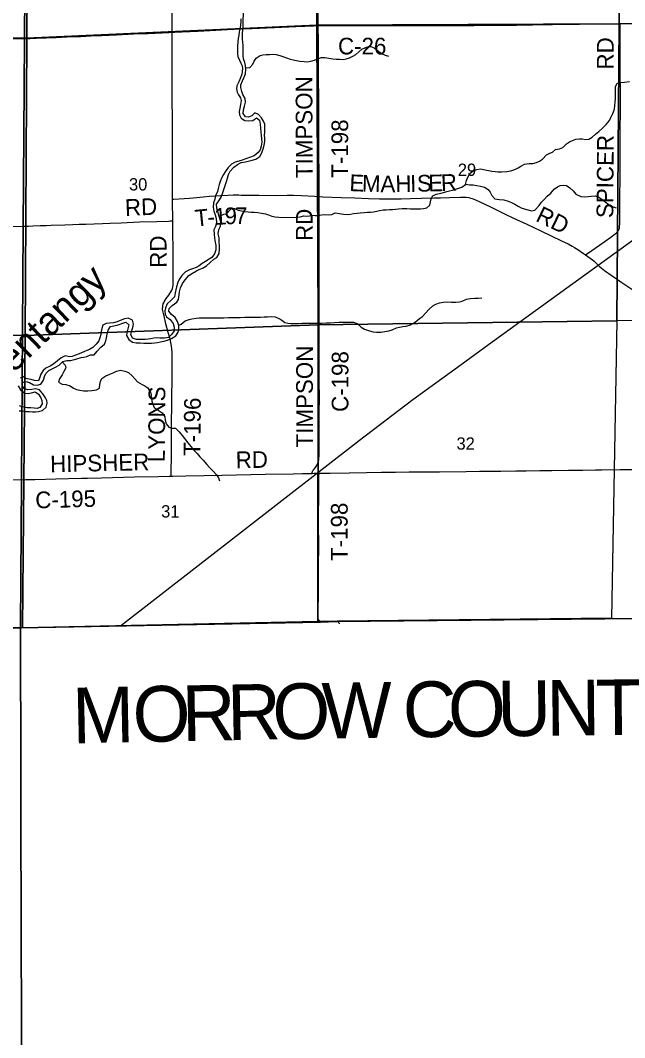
# Model space of a CAD drawing. Extents: x 1584893 to 1934202, y 663575 to 1091909.
# Drawn here: x 1841383 to 1852245, y 956462 to 974741 of the extents above; entities that cross this region are included whole.
import ezdxf

# ---------------------------------------------------------------- set-up
doc = ezdxf.new("R2010")
doc.units = 0
for name, color, linetype in [('GM_X_Adjacent_County', 7, 'Continuous'), ('GM_X_Adjacent_County_Text', 7, 'Continuous'), ('GM_X_County', 7, 'Continuous'), ('GM_X_County_Road', 7, 'Continuous'), ('GM_X_County_Road_Text', 7, 'Continuous'), ('GM_X_Major_River', 7, 'Continuous'), ('GM_X_Major_River_Text', 7, 'Continuous'), ('GM_X_Minor_River', 7, 'Continuous'), ('GM_X_Rail_Line', 7, 'Continuous'), ('GM_X_Section', 7, 'Continuous'), ('GM_X_Section_Text', 7, 'Continuous'), ('GM_X_Township', 7, 'Continuous'), ('GM_X_Township_Road', 7, 'Continuous'), ('GM_X_Township_Road_Text', 7, 'Continuous')]:
    doc.layers.add(name, color=color, linetype=linetype)

msp = doc.modelspace()

# ---------------------------------------------------------------- linework, layer by layer
at = {"layer": 'GM_X_Adjacent_County'}
msp.add_lwpolyline([(1841392, 953202), (1841402, 956488), (1841397, 958575), (1841394, 960342), (1841392, 961182), (1841387, 963824), (1846780, 963929), (1847071, 963938), (1852487, 963992)], dxfattribs=at)
at = {"layer": 'GM_X_County'}
msp.add_lwpolyline([(1852487, 963992), (1847071, 963938), (1846780, 963929), (1841387, 963824), (1841392, 961182), (1841394, 960342), (1841397, 958575), (1841402, 956488), (1841392, 953202)], dxfattribs=at)
at = {"layer": 'GM_X_County_Road'}
for points in [[(1844110, 974526), (1844159, 974530), (1844284, 974536), (1844575, 974549), (1844895, 974566), (1845109, 974576), (1845355, 974588), (1845543, 974594), (1845952, 974613), (1846333, 974631), (1846659, 974644), (1846738, 974647)], [(1846738, 974647), (1846837, 974649), (1847430, 974648), (1847919, 974647), (1848394, 974648), (1848749, 974649), (1849020, 974647), (1849342, 974647), (1849536, 974649), (1849766, 974652), (1850304, 974656), (1850586, 974661), (1850950, 974664), (1851210, 974671), (1851432, 974673), (1851731, 974680), (1852054, 974681), (1852165, 974681)], [(1852165, 974681), (1852339, 974685), (1852528, 974686), (1852724, 974689), (1853041, 974695), (1853330, 974698), (1853643, 974698), (1853900, 974702), (1854097, 974707), (1854466, 974710), (1854695, 974714), (1854798, 974712)], [(1838155, 974444), (1838418, 974444), (1838648, 974441), (1838861, 974440), (1839107, 974439), (1839501, 974434), (1839878, 974430), (1840174, 974426), (1840387, 974425), (1840764, 974422), (1841076, 974417), (1841289, 974415), (1841535, 974415), (1841560, 974416)], [(1841560, 974416), (1841666, 974419), (1842027, 974435), (1842224, 974444), (1842470, 974452), (1842650, 974462), (1842847, 974471), (1843109, 974481), (1843420, 974496), (1843683, 974507), (1844060, 974522), (1844110, 974526)], [(1846627, 966601), (1846630, 966618), (1846634, 966636), (1846643, 966652), (1846656, 966668), (1846687, 966707), (1846705, 966735), (1846721, 966764), (1846728, 966779), (1846738, 966811), (1846746, 966843), (1846751, 966876), (1846753, 966909), (1846755, 967014), (1846756, 967405), (1846757, 967712), (1846758, 967941), (1846756, 968269), (1846756, 968859), (1846755, 969039), (1846757, 969219), (1846757, 969400), (1846757, 969662), (1846755, 970153), (1846756, 970678), (1846756, 970907), (1846755, 971104), (1846755, 971284), (1846756, 971448), (1846755, 971546), (1846755, 971576)], [(1844092, 966552), (1844121, 966552), (1844356, 966555), (1844684, 966562), (1845013, 966569), (1845268, 966576), (1845783, 966585), (1846287, 966593), (1846456, 966598), (1846627, 966601)], [(1846627, 966601), (1846665, 966602), (1846752, 966603)], [(1846752, 966603), (1846767, 966603), (1846950, 966607), (1847292, 966612), (1847604, 966616), (1847874, 966621), (1848124, 966624), (1848374, 966626), (1848674, 966629), (1848916, 966631), (1849395, 966635), (1849634, 966639), (1850021, 966643), (1850287, 966645), (1850473, 966647), (1850721, 966650), (1850934, 966653), (1851237, 966657), (1851494, 966660), (1851721, 966662), (1851836, 966663), (1852164, 966668), (1852420, 966671)], [(1841169, 966484), (1841473, 966488)], [(1841473, 966488), (1841645, 966490), (1842022, 966501), (1842482, 966513), (1842590, 966515), (1842843, 966521), (1843433, 966536), (1843860, 966546), (1844060, 966552), (1844092, 966552)]]:
    msp.add_lwpolyline(points, dxfattribs=at)
at = {"layer": 'GM_X_Major_River'}
for points in [[(1845749, 972434), (1845766, 972496), (1845775, 972562), (1845775, 972624), (1845774, 972680), (1845777, 972730), (1845780, 972804), (1845778, 972876), (1845755, 972927), (1845720, 972992), (1845665, 973047), (1845600, 973077), (1845543, 973028), (1845481, 972999), (1845427, 973006), (1845386, 973065), (1845393, 973135), (1845409, 973199), (1845428, 973271), (1845422, 973339), (1845383, 973408), (1845362, 973463), (1845346, 973533), (1845345, 973583), (1845376, 973653), (1845399, 973705), (1845431, 973780), (1845437, 973862), (1845430, 973931), (1845417, 973981), (1845393, 974050), (1845388, 974112), (1845387, 974162), (1845388, 974212), (1845386, 974280), (1845381, 974353), (1845378, 974403), (1845377, 974453), (1845378, 974509), (1845382, 974563), (1845387, 974635), (1845391, 974707), (1845395, 974894)], [(1845346, 974767), (1845349, 974716), (1845342, 974658), (1845335, 974606), (1845317, 974535), (1845308, 974469), (1845300, 974415), (1845293, 974351), (1845288, 974284), (1845286, 974212), (1845289, 974144), (1845294, 974090), (1845320, 974027), (1845347, 973974), (1845368, 973924), (1845375, 973874), (1845372, 973823), (1845363, 973772), (1845342, 973708), (1845310, 973638), (1845277, 973567), (1845267, 973513), (1845282, 973452), (1845307, 973400), (1845338, 973349), (1845355, 973298), (1845341, 973226), (1845326, 973165), (1845319, 973103), (1845322, 973044), (1845352, 972982), (1845417, 972944), (1845485, 972933), (1845561, 972939), (1845626, 972992), (1845683, 972947), (1845696, 972874), (1845702, 972804), (1845707, 972734)], [(1845707, 972734), (1845714, 972673), (1845716, 972619), (1845721, 972551), (1845714, 972483), (1845692, 972417), (1845657, 972364), (1845584, 972305), (1845499, 972275), (1845435, 972254), (1845368, 972229), (1845310, 972210), (1845246, 972192), (1845177, 972155), (1845120, 972094), (1845066, 972021), (1845033, 971970), (1845004, 971916), (1844972, 971844), (1844957, 971793), (1844940, 971721), (1844925, 971667), (1844893, 971585), (1844876, 971528), (1844856, 971462), (1844849, 971384), (1844859, 971315), (1844884, 971247), (1844902, 971178), (1844909, 971104), (1844891, 971038), (1844862, 970974), (1844864, 970898), (1844873, 970826), (1844887, 970757), (1844894, 970695), (1844895, 970619), (1844873, 970545), (1844826, 970482), (1844775, 970449), (1844712, 970408), (1844651, 970371), (1844596, 970328), (1844544, 970301), (1844475, 970275), (1844423, 970258), (1844350, 970221), (1844283, 970156), (1844235, 970085), (1844214, 970031), (1844187, 969950), (1844178, 969896), (1844166, 969842), (1844151, 969770), (1844088, 969707), (1844022, 969648), (1843991, 969577), (1843980, 969519), (1843986, 969463), (1844011, 969412), (1844076, 969364), (1844131, 969295), (1844147, 969225), (1844148, 969164), (1844105, 969105), (1844044, 969042), (1843975, 969032), (1843893, 969031), (1843839, 969035), (1843781, 969028), (1843731, 969017), (1843681, 969012), (1843625, 969007), (1843545, 969005), (1843469, 969006), (1843400, 969030), (1843371, 969096), (1843384, 969168), (1843402, 969224), (1843415, 969282), (1843396, 969355), (1843321, 969392), (1843255, 969380), (1843176, 969349), (1843124, 969326), (1843056, 969308), (1842983, 969297), (1842925, 969292), (1842867, 969261), (1842845, 969204), (1842836, 969150), (1842829, 969098), (1842814, 969034), (1842795, 968982), (1842747, 968921), (1842686, 968860), (1842626, 968827), (1842575, 968810), (1842521, 968785), (1842440, 968747), (1842377, 968722)], [(1841896, 968447), (1841952, 968478), (1842017, 968509), (1842082, 968548), (1842149, 968609), (1842218, 968631), (1842284, 968632), (1842334, 968641), (1842396, 968658), (1842475, 968684), (1842525, 968689), (1842575, 968700), (1842641, 968729), (1842710, 968733), (1842765, 968798), (1842828, 968869), (1842893, 968922), (1842921, 968983), (1842934, 969035), (1842945, 969105), (1842959, 969173), (1843004, 969242), (1843066, 969253), (1843139, 969270), (1843207, 969294), (1843278, 969319), (1843335, 969268), (1843313, 969196), (1843296, 969128), (1843293, 969078), (1843333, 969007), (1843398, 968960), (1843466, 968946), (1843538, 968947), (1843604, 968943), (1843738, 968940), (1843796, 968945), (1843846, 968954), (1843902, 968963), (1843962, 968978), (1844029, 968996), (1844099, 969023), (1844178, 969072), (1844220, 969139), (1844231, 969193), (1844232, 969255), (1844208, 969332), (1844165, 969403), (1844098, 969458), (1844052, 969513), (1844055, 969563), (1844112, 969618), (1844195, 969677), (1844226, 969728), (1844238, 969810), (1844243, 969860), (1844264, 969936), (1844298, 970012), (1844345, 970081), (1844411, 970154), (1844476, 970200), (1844547, 970239), (1844599, 970264), (1844656, 970289), (1844728, 970330), (1844796, 970392), (1844861, 970447), (1844912, 970482), (1844955, 970551), (1844961, 970629), (1844960, 970688), (1844959, 970760), (1844955, 970834), (1844941, 970905), (1844948, 970985), (1844981, 971044), (1844989, 971110), (1844968, 971179), (1844950, 971241), (1844933, 971300), (1844914, 971368), (1844908, 971437), (1844951, 971500), (1844990, 971561), (1845016, 971627), (1845039, 971703), (1845056, 971754), (1845086, 971846), (1845106, 971908), (1845127, 971968), (1845152, 972031), (1845218, 972104), (1845289, 972153), (1845355, 972185), (1845428, 972200), (1845480, 972209), (1845548, 972228), (1845617, 972248), (1845688, 972295), (1845725, 972362), (1845749, 972434)], [(1842377, 968722), (1842317, 968703), (1842267, 968696), (1842191, 968714), (1842117, 968679), (1842053, 968625), (1841982, 968572), (1841916, 968529), (1841843, 968491), (1841792, 968452), (1841751, 968384), (1841735, 968328), (1841708, 968261), (1841638, 968272), (1841577, 968286), (1841507, 968301), (1841470, 968313)], [(1841359, 967723), (1841427, 967723), (1841482, 967714), (1841546, 967711), (1841600, 967708), (1841658, 967706), (1841712, 967711), (1841781, 967732), (1841844, 967789), (1841867, 967860), (1841856, 967911), (1841832, 967961), (1841785, 968029), (1841725, 968102), (1841657, 968117), (1841589, 968105), (1841517, 968102), (1841453, 968126), (1841416, 968177), (1841415, 968233), (1841482, 968251), (1841547, 968234), (1841617, 968192), (1841684, 968183), (1841753, 968206), (1841800, 968273), (1841816, 968339), (1841839, 968394), (1841896, 968447)], [(1841470, 968313), (1841438, 968337), (1841377, 968310)], [(1841344, 968174), (1841383, 968103), (1841455, 968043), (1841521, 968038), (1841582, 968051), (1841652, 968065), (1841711, 968026), (1841750, 967961), (1841767, 967911), (1841773, 967848), (1841736, 967785), (1841686, 967768), (1841632, 967771), (1841574, 967776), (1841504, 967776), (1841418, 967798), (1841367, 967813)]]:
    msp.add_lwpolyline(points, dxfattribs=at)
at = {"layer": 'GM_X_Minor_River'}
for points in [[(1845435, 973885), (1845505, 973891), (1845559, 973954), (1845588, 974009), (1845619, 974063), (1845694, 974108), (1845744, 974119), (1845800, 974127), (1845860, 974130), (1845926, 974131), (1845982, 974126), (1846046, 974110), (1846103, 974089), (1846165, 974068), (1846232, 974046), (1846288, 974031), (1846344, 974020), (1846407, 974008), (1846485, 973999), (1846537, 973998), (1846607, 974008), (1846668, 974025), (1846740, 974058), (1846795, 974073), (1846855, 974071), (1846926, 974062), (1847002, 974052), (1847068, 974045), (1847122, 974042), (1847184, 974040), (1847238, 974049), (1847302, 974070), (1847361, 974095), (1847414, 974130), (1847467, 974175), (1847524, 974222), (1847576, 974247), (1847630, 974266), (1847683, 974269), (1847742, 974247), (1847797, 974202), (1847874, 974146), (1847943, 974117), (1847999, 974100)], [(1850949, 972372), (1851002, 972419), (1851073, 972435), (1851135, 972456), (1851202, 972523), (1851253, 972556), (1851306, 972583), (1851368, 972604), (1851432, 972612), (1851484, 972611), (1851550, 972602), (1851600, 972607), (1851659, 972640), (1851722, 972696), (1851783, 972745), (1851842, 972800), (1851915, 972869), (1851971, 972940), (1851994, 972998), (1852030, 973067), (1852063, 973145), (1852071, 973211), (1852076, 973271), (1852081, 973335), (1852081, 973407), (1852079, 973493), (1852078, 973549), (1852111, 973609), (1852177, 973621), (1852243, 973630), (1852330, 973640)], [(1844959, 971212), (1844973, 971221), (1845040, 971260), (1845094, 971262), (1845129, 971314), (1845182, 971367), (1845234, 971358), (1845301, 971330), (1845357, 971317), (1845415, 971308), (1845477, 971303), (1845529, 971297), (1845585, 971294), (1845650, 971287), (1845720, 971279), (1845790, 971262), (1845843, 971245), (1845905, 971223), (1845961, 971210), (1846029, 971207), (1846288, 971201), (1846340, 971202), (1846414, 971211), (1846477, 971226), (1846529, 971222), (1846581, 971227), (1846631, 971238), (1846683, 971237), (1846739, 971234), (1846795, 971245), (1846847, 971252), (1846925, 971246), (1846981, 971255), (1847040, 971280), (1847122, 971272), (1847193, 971259), (1847261, 971255), (1847315, 971260), (1847371, 971269), (1847438, 971278), (1847490, 971283), (1847560, 971291), (1847620, 971294), (1847676, 971295), (1847730, 971298), (1847788, 971311), (1847838, 971322), (1847903, 971334), (1847957, 971339), (1848019, 971340), (1848071, 971345), (1848129, 971350), (1848183, 971356), (1848249, 971361), (1848329, 971359), (1848397, 971356), (1848457, 971355), (1848513, 971354), (1848575, 971356), (1848631, 971361), (1848689, 971370), (1848746, 971419), (1848757, 971481), (1848766, 971533), (1848798, 971590), (1848856, 971619), (1848920, 971630), (1848991, 971650), (1849047, 971667), (1849099, 971680), (1849150, 971691), (1849204, 971708), (1849262, 971725), (1849317, 971742), (1849384, 971789), (1849405, 971864), (1849428, 971926), (1849460, 971990), (1849527, 972044), (1849589, 972063), (1849657, 972072), (1849735, 972056), (1849797, 972041), (1849857, 972032), (1849916, 972024), (1849968, 972019), (1850030, 972018), (1850128, 972026), (1850199, 972038), (1850273, 972059), (1850332, 972088), (1850382, 972119), (1850443, 972156), (1850527, 972168), (1850595, 972169), (1850663, 972185), (1850716, 972210), (1850771, 972249), (1850840, 972322), (1850899, 972353), (1850949, 972372)], [(1849386, 971798), (1849457, 971783), (1849525, 971784), (1849587, 971776), (1849655, 971759), (1849726, 971743), (1849794, 971704), (1849827, 971653), (1849855, 971596), (1849914, 971533), (1849996, 971519), (1850076, 971514), (1850151, 971494), (1850214, 971465), (1850270, 971435), (1850329, 971400), (1850384, 971375), (1850440, 971356), (1850502, 971336), (1850569, 971319), (1850631, 971330), (1850711, 971414), (1850752, 971473), (1850806, 971528), (1850853, 971580), (1850916, 971638), (1850979, 971705), (1851036, 971750), (1851089, 971773), (1851141, 971780), (1851201, 971771), (1851260, 971732), (1851317, 971680), (1851369, 971615), (1851456, 971575), (1851516, 971570), (1851590, 971576), (1851644, 971583), (1851714, 971586), (1851780, 971562), (1851839, 971521), (1851918, 971461), (1851973, 971426), (1852040, 971392), (1852092, 971373)], [(1844230, 969261), (1844273, 969282), (1844348, 969339), (1844416, 969367), (1844466, 969376), (1844541, 969389), (1844595, 969394), (1844645, 969397), (1844709, 969397), (1844903, 969393), (1844971, 969394), (1845043, 969394), (1845127, 969399), (1845185, 969400), (1845259, 969400), (1845335, 969402), (1845417, 969405), (1845491, 969407), (1845557, 969408), (1845627, 969410), (1845699, 969409), (1845765, 969416), (1845823, 969416), (1845893, 969417), (1845961, 969415), (1846032, 969386), (1846085, 969353), (1846139, 969314), (1846190, 969300), (1846244, 969295), (1846316, 969296), (1846386, 969296), (1846442, 969299), (1846498, 969300), (1846588, 969300), (1846644, 969301), (1846702, 969300), (1846796, 969302), (1846880, 969304), (1846956, 969307), (1847030, 969313), (1847106, 969317), (1847164, 969316), (1847228, 969315), (1847300, 969317), (1847372, 969318), (1847438, 969292), (1847508, 969229), (1847569, 969189), (1847657, 969160), (1847726, 969142), (1847782, 969139), (1847860, 969139), (1847936, 969148), (1848005, 969160), (1848069, 969183), (1848144, 969214), (1848200, 969228), (1848256, 969241), (1848320, 969246), (1848397, 969268), (1848482, 969319), (1848557, 969381), (1848610, 969418), (1848667, 969479), (1848727, 969546), (1848796, 969611), (1848850, 969640), (1848919, 969665), (1848991, 969679), (1849069, 969684), (1849135, 969680), (1849211, 969679), (1849275, 969683), (1849325, 969694), (1849404, 969729), (1849476, 969743), (1849554, 969748), (1849610, 969749), (1849679, 969753)], [(1842138, 968599), (1842190, 968548), (1842201, 968495), (1842167, 968432), (1842132, 968370), (1842085, 968299), (1842067, 968237), (1842133, 968204), (1842200, 968198), (1842276, 968171), (1842341, 968133), (1842394, 968108), (1842454, 968095), (1842516, 968084), (1842598, 968086), (1842670, 968092), (1842750, 968099), (1842807, 968132), (1842814, 968200), (1842823, 968252), (1842846, 968307), (1842921, 968356), (1842994, 968384), (1843053, 968409), (1843111, 968438), (1843184, 968457), (1843261, 968439), (1843327, 968412), (1843391, 968356), (1843440, 968301), (1843489, 968248), (1843572, 968198), (1843623, 968171), (1843677, 968136), (1843725, 968062), (1843734, 968004), (1843741, 967948), (1843747, 967897), (1843764, 967843), (1843791, 967786), (1843880, 967724), (1843935, 967689), (1843977, 967616), (1843986, 967558), (1844001, 967491), (1844052, 967430), (1844107, 967415), (1844169, 967413), (1844238, 967346), (1844290, 967282), (1844331, 967228), (1844394, 967152), (1844450, 967083), (1844509, 967013), (1844559, 966956), (1844612, 966897), (1844669, 966837), (1844733, 966760), (1844780, 966709), (1844847, 966643), (1844911, 966576), (1844942, 966523), (1844961, 966464)]]:
    msp.add_lwpolyline(points, dxfattribs=at)
at = {"layer": 'GM_X_Rail_Line'}
msp.add_lwpolyline([(1843186, 963859), (1847480, 967198), (1848435, 967928), (1849305, 968558), (1849800, 968917), (1855926, 973347)], dxfattribs=at)
at = {"layer": 'GM_X_Section'}
for points in [[(1852199, 980028), (1857493, 980105), (1857385, 974712), (1852149, 974677)], [(1841535, 979712), (1844949, 979989), (1846705, 980015), (1846710, 974657), (1841497, 974418)], [(1846705, 980015), (1852199, 980028), (1852149, 974677), (1846710, 974657)], [(1836169, 979777), (1841535, 979712), (1841497, 974418), (1836118, 974458)], [(1841497, 974418), (1846710, 974657), (1846738, 969270), (1841469, 969077)], [(1846710, 974657), (1852149, 974677), (1852104, 969344), (1846738, 969270)], [(1852149, 974677), (1857385, 974712), (1857325, 969408), (1852104, 969344)], [(1836118, 974458), (1841497, 974418), (1841469, 969077), (1836100, 969135)], [(1846738, 969270), (1852104, 969344), (1852006, 963999), (1847086, 963946), (1846730, 963939)], [(1836100, 969135), (1841469, 969077), (1841420, 963828), (1836085, 963804)], [(1841469, 969077), (1846738, 969270), (1846730, 963939), (1841420, 963828)]]:
    msp.add_lwpolyline(points, close=True, dxfattribs=at)
at = {"layer": 'GM_X_Township'}
for points in [[(1852487, 963992), (1847071, 963938), (1846780, 963929), (1841387, 963824), (1841405, 966456), (1841436, 971009), (1841459, 974382), (1841496, 979677), (1841532, 984992), (1841533, 985009), (1841872, 985027), (1842914, 985093), (1844196, 985194), (1845074, 985259), (1845572, 985289), (1846658, 985379), (1846800, 985384), (1849534, 985395), (1852293, 985374)], [(1809298, 953687), (1809358, 958555), (1809388, 963837), (1815539, 963824), (1823776, 963824), (1832077, 963824), (1839237, 963824), (1841387, 963824), (1841392, 961182), (1841394, 960342), (1841397, 958575), (1841402, 956488), (1841392, 953202)]]:
    msp.add_lwpolyline(points, dxfattribs=at)
msp.add_lwpolyline([(1809388, 963837), (1809397, 965194), (1809409, 966524), (1809470, 974481), (1809490, 979763), (1809554, 985051), (1810918, 985033), (1820580, 985048), (1828627, 985061), (1836217, 985098), (1839819, 985043), (1841171, 985014), (1841533, 985009), (1841532, 984992), (1841496, 979677), (1841459, 974382), (1841436, 971009), (1841405, 966456), (1841387, 963824), (1839237, 963824), (1832077, 963824), (1823776, 963824), (1815539, 963824)], close=True, dxfattribs=at)
at = {"layer": 'GM_X_Township_Road'}
for points in [[(1844110, 974526), (1844110, 974576), (1844110, 974708), (1844114, 975053)], [(1846738, 974647), (1846738, 974720), (1846735, 974983)], [(1846755, 971576), (1846755, 971768), (1846755, 971957), (1846751, 972365), (1846750, 972644), (1846749, 972775), (1846748, 972988), (1846748, 973153), (1846748, 973333), (1846745, 973711), (1846743, 973908), (1846743, 974051), (1846741, 974229), (1846740, 974402), (1846739, 974597), (1846738, 974647)], [(1851540, 970525), (1851566, 970544), (1851579, 970553), (1851793, 970704), (1851994, 970845), (1852077, 970903), (1852098, 970921), (1852111, 970935), (1852122, 970947), (1852131, 970961), (1852139, 970975), (1852145, 970990), (1852152, 971008), (1852155, 971028), (1852156, 971099), (1852156, 971152), (1852156, 971205), (1852156, 971272), (1852159, 971349), (1852158, 971431), (1852161, 971653), (1852164, 971824), (1852166, 972184), (1852165, 972430), (1852165, 972828), (1852169, 973053), (1852169, 973298), (1852168, 973478), (1852166, 973773), (1852166, 973937), (1852166, 974084), (1852166, 974379), (1852164, 974595), (1852164, 974641), (1852165, 974681)], [(1844119, 971527), (1844118, 971838), (1844119, 972199), (1844117, 972543), (1844115, 972822), (1844115, 972970), (1844113, 973314), (1844113, 973658), (1844111, 973954), (1844110, 974265), (1844110, 974478), (1844110, 974526)], [(1844119, 971527), (1844142, 971528), (1844328, 971540), (1844426, 971548), (1844488, 971554)], [(1844125, 971138), (1844124, 971165), (1844119, 971477), (1844119, 971527)], [(1844488, 971554), (1844671, 971572), (1844785, 971581), (1844982, 971594), (1845113, 971600), (1845211, 971603), (1845310, 971603), (1845351, 971602)], [(1845351, 971602), (1845474, 971598), (1845671, 971597), (1845966, 971595), (1846180, 971597), (1846292, 971600), (1846434, 971595), (1846669, 971581), (1846755, 971576)], [(1846755, 971576), (1846819, 971571), (1847147, 971559), (1847393, 971550), (1847639, 971539), (1847836, 971533), (1847934, 971532), (1848066, 971531), (1848230, 971533), (1848394, 971537), (1848591, 971544), (1848820, 971549), (1848935, 971552), (1849099, 971558), (1849296, 971566), (1849345, 971566), (1849394, 971563), (1849443, 971555), (1849475, 971547), (1849506, 971537), (1849567, 971513), (1849642, 971479), (1849834, 971387), (1850085, 971265), (1850234, 971195), (1850486, 971076), (1850738, 970956), (1851108, 970780), (1851227, 970724), (1851300, 970686), (1851346, 970661), (1851401, 970626), (1851505, 970550), (1851540, 970525)], [(1841737, 971052), (1841738, 971052), (1841853, 971057), (1841934, 971060), (1842180, 971068), (1842328, 971073), (1842442, 971076), (1842557, 971081), (1842704, 971086), (1842862, 971092), (1842995, 971096), (1843195, 971105), (1843523, 971118), (1843834, 971128), (1844047, 971135), (1844080, 971136), (1844125, 971138)], [(1844067, 969034), (1844039, 969135), (1844000, 969288), (1843966, 969429), (1843954, 969475), (1843945, 969519), (1843941, 969552), (1843941, 969571), (1843942, 969585), (1843946, 969619), (1843952, 969647), (1843959, 969666), (1843968, 969685), (1843984, 969714), (1844002, 969741), (1844053, 969805), (1844072, 969832), (1844089, 969860), (1844104, 969890), (1844115, 969920), (1844124, 969952), (1844129, 969984), (1844132, 970017), (1844132, 970070), (1844131, 970361), (1844129, 970640), (1844126, 970919), (1844125, 971138)], [(1841247, 971034), (1841443, 971041), (1841531, 971044)], [(1841531, 971044), (1841607, 971047), (1841737, 971052)], [(1851540, 970525), (1851665, 970435), (1851696, 970411), (1851728, 970382), (1851775, 970337), (1851787, 970326)], [(1851787, 970326), (1851824, 970295), (1851883, 970248), (1852021, 970149), (1852195, 970031), (1852391, 969901)], [(1844092, 966552), (1844092, 966582), (1844094, 966633), (1844097, 966919), (1844099, 967247), (1844102, 967543), (1844105, 967786), (1844106, 967922), (1844108, 968070), (1844109, 968200), (1844112, 968461), (1844113, 968688), (1844112, 968773), (1844107, 968838), (1844101, 968887), (1844089, 968951), (1844082, 968981), (1844074, 969012), (1844067, 969034)], [(1846765, 963942), (1846758, 963950), (1846749, 963960), (1846743, 963974), (1846739, 963997), (1846736, 964044), (1846739, 964155), (1846741, 964408), (1846743, 964649), (1846745, 964960), (1846747, 965289), (1846744, 965699), (1846744, 965879), (1846747, 966164), (1846751, 966469), (1846751, 966552), (1846752, 966603)], [(1846926, 963935), (1846923, 963935), (1846841, 963930), (1846809, 963931), (1846792, 963933), (1846779, 963935), (1846772, 963938), (1846765, 963942)], [(1847120, 963897), (1847117, 963903), (1847113, 963910), (1847107, 963917), (1847100, 963924), (1847087, 963932), (1847071, 963938), (1847054, 963940), (1847022, 963941), (1846926, 963935)]]:
    msp.add_lwpolyline(points, dxfattribs=at)

# ---------------------------------------------------------------- texts
at = {"layer": 'GM_X_Adjacent_County_Text'}
for s, rotation, p in [('M', 1.1566, (1842325, 961749)), ('O', 1.1538, (1843411, 961771)), ('R', 1.1378, (1844296, 961789)), ('R', 1.0787, (1845109, 961805)), ('O', 0.9602, (1845922, 961820)), ('W', 0.8568, (1846806, 961835)), ('C', 0.6817, (1848262, 961857)), ('O', 0.6166, (1849075, 961866)), ('U', 0.597, (1849960, 961876)), ('N', 0.5981, (1850844, 961885)), ('T', 0.5979, (1851728, 961894))]:
    msp.add_text(s, height=1000, rotation=rotation, dxfattribs=at).set_placement(p)
at = {"layer": 'GM_X_County_Road_Text'}
for s, rotation, p in [('C-26', 0, (1847093, 974128)), ('RD', 90, (1846636, 970777)), ('TIMPSON', 90, (1846641, 967068)), ('C-198', 90.0011, (1847280, 967705)), ('HIPSHER', 1.2838, (1841921, 966619)), ('RD', 0.9872, (1845256, 966693)), ('C-195', 1.6641, (1841655, 965971))]:
    msp.add_text(s, height=300, rotation=rotation, dxfattribs=at).set_placement(p)
at = {"layer": 'GM_X_Major_River_Text'}
msp.add_text('Olentangy', height=500.1, rotation=44.0104, dxfattribs=at).set_placement((1840773, 967921))
at = {"layer": 'GM_X_Section_Text'}
for s, p in [('29', (1849247, 971946)), ('30', (1843336, 971684)), ('32', (1849223, 967027)), ('31', (1843914, 965808))]:
    msp.add_text(s, height=221, rotation=0, dxfattribs=at).set_placement(p)
at = {"layer": 'GM_X_Township_Road_Text'}
for s, rotation, p in [('RD', 90, (1852048, 973857)), ('TIMPSON', 90.1555, (1846636, 971908)), ('T-198', 90, (1847275, 971913)), ('SPICER', 89.5982, (1852040, 971187)), ('E', 357.6551, (1847293, 971674)), ('M', 357.9534, (1847519, 971665)), ('A', 359.8892, (1847856, 971653)), ('H', 1.2243, (1848127, 971653)), ('I', 1.2964, (1848392, 971658)), ('S', 1.2958, (1848515, 971661)), ('E', 1.3506, (1848718, 971666)), ('R', 2.4548, (1848948, 971671)), ('RD', 2.4686, (1843269, 971225)), ('T', 5.6534, (1844533, 971034)), ('1', 3.2595, (1844876, 971064)), ('9', 2.0144, (1845059, 971075)), ('7', 359.6774, (1845240, 971081)), ('RD', 334.3218, (1850629, 971143)), ('-', 3.7731, (1844754, 971056)), ('RD', 90.4889, (1844014, 970296)), ('LYONS', 89.5904, (1843979, 966801)), ('T-196', 89.4403, (1844617, 966913)), ('T-198', 90, (1847266, 965027))]:
    msp.add_text(s, height=300, rotation=rotation, dxfattribs=at).set_placement(p)

doc.saveas('drawing.dxf')
